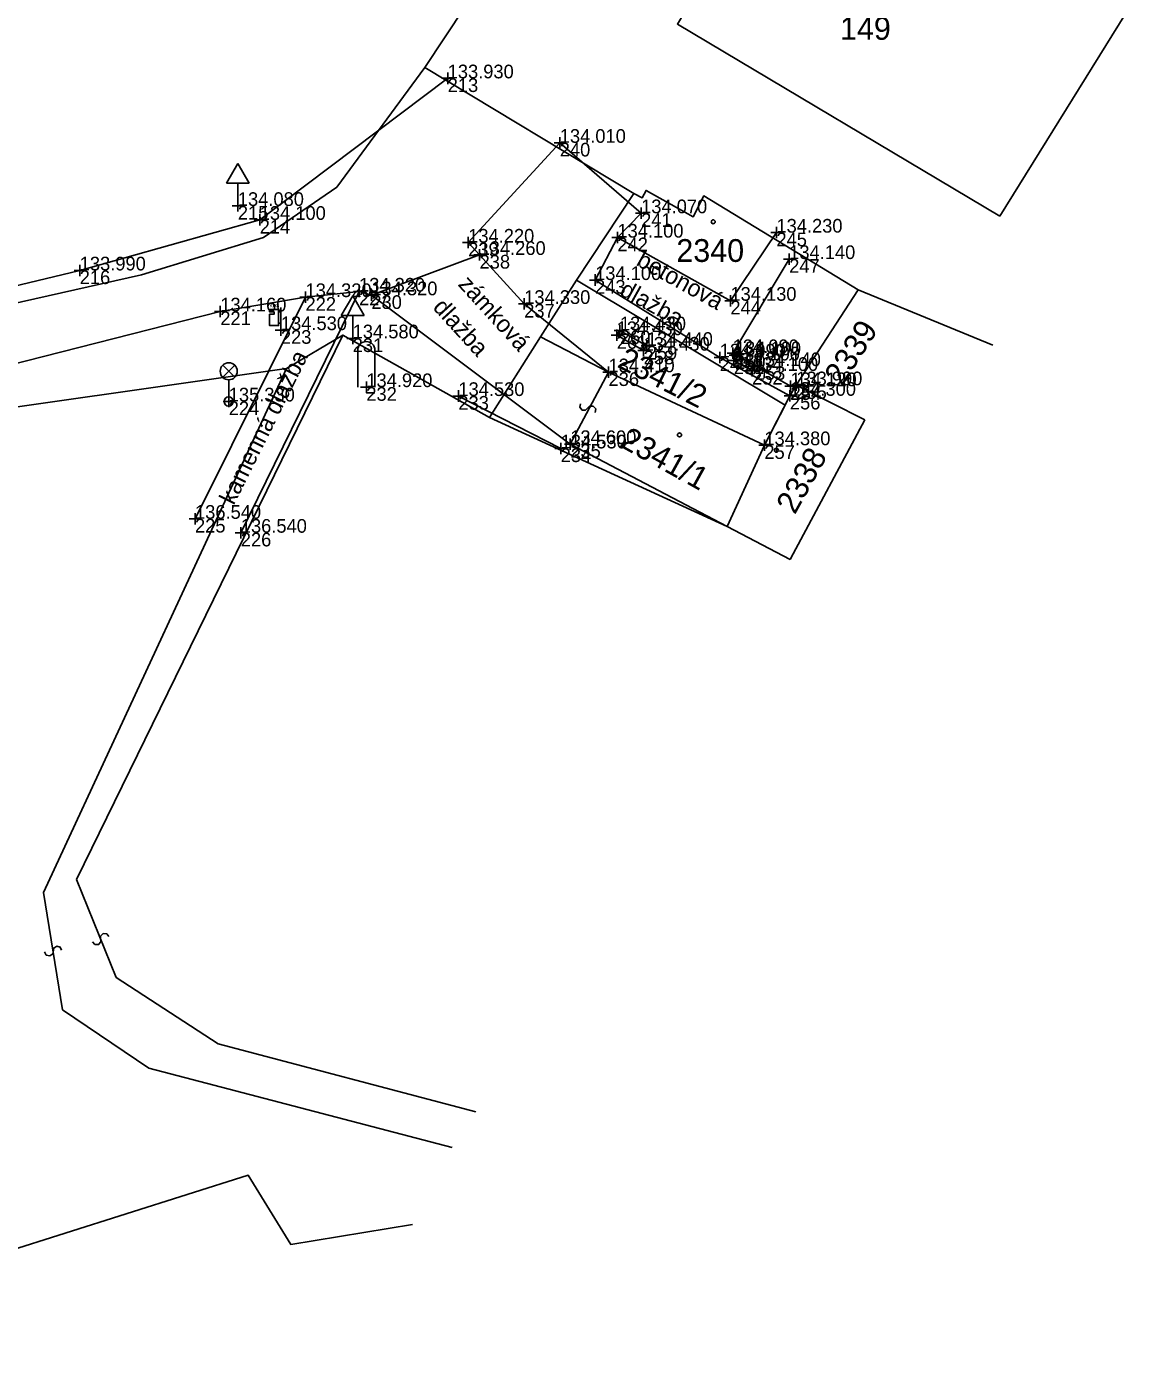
# Model space of a CAD drawing. Extents: x -747268 to -747054, y -964730 to -964532.
# Drawn here: x -747124.6 to -747076.4, y -964717 to -964658.8 of the extents above; entities that cross this region are included whole.
import ezdxf

# ---------------------------------------------------------------- set-up
doc = ezdxf.new("R2010")
doc.units = 0
for name, color, linetype in [('Body polohopisu', 7, 'Continuous'), ('Budovy', 7, 'Continuous'), ('Doplňkové značky', 7, 'Continuous'), ('KM', 7, 'Continuous'), ('Ploty_opěrné zdi', 7, 'Continuous'), ('Popisy objektů_povrchů', 7, 'Continuous'), ('Rozhraní ploch', 7, 'Continuous'), ('Stromy_porost', 7, 'Continuous'), ('Vnitřní kresba', 7, 'Continuous'), ('Výšky bodů', 7, 'Continuous'), ('Značky IS', 7, 'Continuous'), ('Čísla bodů', 7, 'Continuous')]:
    doc.layers.add(name, color=color, linetype=linetype)

msp = doc.modelspace()

# ---------------------------------------------------------------- linework, layer by layer
at = {"layer": 'Body polohopisu'}
for p, q in [((-747106.13, -964661.08), (-747106.38, -964661.08)), ((-747106.13, -964661.08), (-747106.13, -964660.83)), ((-747106.13, -964661.08), (-747105.88, -964661.08)), ((-747106.13, -964661.08), (-747106.13, -964661.33)), ((-747101.21, -964663.91), (-747101.46, -964663.91)), ((-747101.21, -964663.91), (-747101.21, -964663.66)), ((-747101.21, -964663.91), (-747100.96, -964663.91)), ((-747101.21, -964663.91), (-747101.21, -964664.16)), ((-747115.34, -964666.68), (-747115.34, -964666.43)), ((-747115.34, -964666.68), (-747115.59, -964666.68)), ((-747115.34, -964666.68), (-747115.09, -964666.68)), ((-747115.34, -964666.68), (-747115.34, -964666.93)), ((-747114.38, -964667.29), (-747114.38, -964667.04)), ((-747097.64, -964667), (-747097.89, -964667)), ((-747097.64, -964667), (-747097.64, -964666.75)), ((-747097.64, -964667), (-747097.39, -964667)), ((-747097.64, -964667), (-747097.64, -964667.25)), ((-747114.38, -964667.29), (-747114.63, -964667.29)), ((-747114.38, -964667.29), (-747114.13, -964667.29)), ((-747114.38, -964667.29), (-747114.38, -964667.54)), ((-747091.7, -964667.85), (-747091.7, -964667.6)), ((-747105.23, -964668.29), (-747105.23, -964668.04)), ((-747098.68, -964668.07), (-747098.93, -964668.07)), ((-747098.68, -964668.07), (-747098.68, -964667.82)), ((-747098.68, -964668.07), (-747098.43, -964668.07)), ((-747098.68, -964668.07), (-747098.68, -964668.32)), ((-747091.7, -964667.85), (-747091.95, -964667.85)), ((-747091.7, -964667.85), (-747091.45, -964667.85)), ((-747091.7, -964667.85), (-747091.7, -964668.1)), ((-747105.23, -964668.29), (-747105.48, -964668.29)), ((-747105.23, -964668.29), (-747104.98, -964668.29)), ((-747105.23, -964668.29), (-747105.23, -964668.54)), ((-747104.73, -964668.83), (-747104.73, -964668.58)), ((-747091.14, -964669.01), (-747091.14, -964668.76)), ((-747122.28, -964669.51), (-747122.28, -964669.26)), ((-747104.73, -964668.83), (-747104.98, -964668.83)), ((-747104.73, -964668.83), (-747104.48, -964668.83)), ((-747104.73, -964668.83), (-747104.73, -964669.08)), ((-747091.14, -964669.01), (-747091.39, -964669.01)), ((-747091.14, -964669.01), (-747090.89, -964669.01)), ((-747091.14, -964669.01), (-747091.14, -964669.26)), ((-747122.28, -964669.51), (-747122.53, -964669.51)), ((-747122.28, -964669.51), (-747122.03, -964669.51)), ((-747122.28, -964669.51), (-747122.28, -964669.76)), ((-747099.66, -964669.93), (-747099.91, -964669.93)), ((-747099.66, -964669.93), (-747099.66, -964669.68)), ((-747099.66, -964669.93), (-747099.41, -964669.93)), ((-747099.66, -964669.93), (-747099.66, -964670.18)), ((-747112.37, -964670.68), (-747112.37, -964670.43)), ((-747110.02, -964670.44), (-747110.27, -964670.44)), ((-747110.02, -964670.44), (-747110.02, -964670.19)), ((-747110.02, -964670.44), (-747109.77, -964670.44)), ((-747110.02, -964670.44), (-747110.02, -964670.69)), ((-747109.48, -964670.6), (-747109.48, -964670.35)), ((-747116.11, -964671.31), (-747116.11, -964671.06)), ((-747112.37, -964670.68), (-747112.62, -964670.68)), ((-747112.37, -964670.68), (-747112.12, -964670.68)), ((-747112.37, -964670.68), (-747112.37, -964670.93)), ((-747109.48, -964670.6), (-747109.73, -964670.6)), ((-747109.48, -964670.6), (-747109.23, -964670.6)), ((-747109.48, -964670.6), (-747109.48, -964670.85)), ((-747102.77, -964670.98), (-747103.02, -964670.98)), ((-747102.77, -964670.98), (-747102.77, -964670.73)), ((-747102.77, -964670.98), (-747102.52, -964670.98)), ((-747102.77, -964670.98), (-747102.77, -964671.23)), ((-747093.72, -964670.84), (-747093.97, -964670.84)), ((-747093.72, -964670.84), (-747093.72, -964670.59)), ((-747093.72, -964670.84), (-747093.47, -964670.84)), ((-747093.72, -964670.84), (-747093.72, -964671.09)), ((-747116.11, -964671.31), (-747116.36, -964671.31)), ((-747116.11, -964671.31), (-747115.86, -964671.31)), ((-747116.11, -964671.31), (-747116.11, -964671.56)), ((-747113.45, -964672.13), (-747113.7, -964672.13)), ((-747113.45, -964672.13), (-747113.45, -964671.88)), ((-747113.45, -964672.13), (-747113.2, -964672.13)), ((-747113.45, -964672.13), (-747113.45, -964672.38)), ((-747110.3, -964672.49), (-747110.3, -964672.24)), ((-747098.57, -964672.14), (-747098.82, -964672.14)), ((-747098.71, -964672.35), (-747098.71, -964672.1)), ((-747098.57, -964672.14), (-747098.57, -964671.89)), ((-747098.57, -964672.14), (-747098.32, -964672.14)), ((-747098.57, -964672.14), (-747098.57, -964672.39)), ((-747110.3, -964672.49), (-747110.55, -964672.49)), ((-747110.3, -964672.49), (-747110.05, -964672.49)), ((-747110.3, -964672.49), (-747110.3, -964672.74)), ((-747098.71, -964672.35), (-747098.96, -964672.35)), ((-747098.71, -964672.35), (-747098.46, -964672.35)), ((-747098.71, -964672.35), (-747098.71, -964672.6)), ((-747097.39, -964672.82), (-747097.64, -964672.82)), ((-747097.53, -964673.03), (-747097.53, -964672.78)), ((-747097.39, -964672.82), (-747097.39, -964672.57)), ((-747097.39, -964672.82), (-747097.14, -964672.82)), ((-747097.39, -964672.82), (-747097.39, -964673.07)), ((-747097.53, -964673.03), (-747097.78, -964673.03)), ((-747097.53, -964673.03), (-747097.28, -964673.03)), ((-747097.53, -964673.03), (-747097.53, -964673.28)), ((-747094.19, -964673.33), (-747094.44, -964673.33)), ((-747094.19, -964673.33), (-747094.19, -964673.08)), ((-747094.19, -964673.33), (-747093.94, -964673.33)), ((-747094.19, -964673.33), (-747094.19, -964673.58)), ((-747093.62, -964673.14), (-747093.87, -964673.14)), ((-747093.52, -964673.23), (-747093.77, -964673.23)), ((-747093.62, -964673.14), (-747093.62, -964672.89)), ((-747093.62, -964673.14), (-747093.37, -964673.14)), ((-747093.62, -964673.14), (-747093.62, -964673.39)), ((-747093.57, -964673.46), (-747093.57, -964673.21)), ((-747093.52, -964673.23), (-747093.52, -964672.98)), ((-747093.52, -964673.23), (-747093.27, -964673.23)), ((-747093.52, -964673.23), (-747093.52, -964673.48)), ((-747099.07, -964673.98), (-747099.32, -964673.98)), ((-747099.07, -964673.98), (-747099.07, -964673.73)), ((-747099.07, -964673.98), (-747098.82, -964673.98)), ((-747099.07, -964673.98), (-747099.07, -964674.23)), ((-747093.57, -964673.46), (-747093.82, -964673.46)), ((-747093.57, -964673.46), (-747093.32, -964673.46)), ((-747093.57, -964673.46), (-747093.57, -964673.71)), ((-747092.77, -964673.92), (-747093.02, -964673.92)), ((-747092.65, -964673.71), (-747092.9, -964673.71)), ((-747092.77, -964673.92), (-747092.77, -964673.67)), ((-747092.77, -964673.92), (-747092.52, -964673.92)), ((-747092.77, -964673.92), (-747092.77, -964674.17)), ((-747092.65, -964673.71), (-747092.65, -964673.46)), ((-747092.65, -964673.71), (-747092.4, -964673.71)), ((-747092.65, -964673.71), (-747092.65, -964673.96)), ((-747109.7, -964674.63), (-747109.7, -964674.38)), ((-747091.08, -964674.59), (-747091.33, -964674.59)), ((-747091.08, -964674.59), (-747091.08, -964674.34)), ((-747090.83, -964674.55), (-747091.08, -964674.55)), ((-747091.08, -964674.59), (-747090.83, -964674.59)), ((-747091.08, -964674.59), (-747091.08, -964674.84)), ((-747090.83, -964674.55), (-747090.83, -964674.3)), ((-747090.83, -964674.55), (-747090.58, -964674.55)), ((-747090.83, -964674.55), (-747090.83, -964674.8)), ((-747115.74, -964675.26), (-747115.74, -964675.01)), ((-747109.7, -964674.63), (-747109.95, -964674.63)), ((-747109.7, -964674.63), (-747109.45, -964674.63)), ((-747109.7, -964674.63), (-747109.7, -964674.88)), ((-747105.66, -964675.02), (-747105.91, -964675.02)), ((-747105.66, -964675.02), (-747105.66, -964674.77)), ((-747105.66, -964675.02), (-747105.41, -964675.02)), ((-747105.66, -964675.02), (-747105.66, -964675.27)), ((-747091.11, -964675.01), (-747091.36, -964675.01)), ((-747091.11, -964675.01), (-747091.11, -964674.76)), ((-747091.11, -964675.01), (-747090.86, -964675.01)), ((-747091.11, -964675.01), (-747091.11, -964675.26)), ((-747115.74, -964675.26), (-747115.99, -964675.26)), ((-747115.74, -964675.26), (-747115.49, -964675.26)), ((-747115.74, -964675.26), (-747115.74, -964675.51)), ((-747100.75, -964677.13), (-747100.75, -964676.88)), ((-747092.23, -964677.18), (-747092.23, -964676.93)), ((-747101.17, -964677.32), (-747101.42, -964677.32)), ((-747101.17, -964677.32), (-747101.17, -964677.07)), ((-747101.17, -964677.32), (-747100.92, -964677.32)), ((-747101.17, -964677.32), (-747101.17, -964677.57)), ((-747100.75, -964677.13), (-747101, -964677.13)), ((-747100.75, -964677.13), (-747100.5, -964677.13)), ((-747100.75, -964677.13), (-747100.75, -964677.38)), ((-747092.23, -964677.18), (-747092.48, -964677.18)), ((-747092.23, -964677.18), (-747091.98, -964677.18)), ((-747092.23, -964677.18), (-747092.23, -964677.43)), ((-747117.22, -964680.41), (-747117.47, -964680.41)), ((-747117.22, -964680.41), (-747117.22, -964680.16)), ((-747117.22, -964680.41), (-747116.97, -964680.41)), ((-747117.22, -964680.41), (-747117.22, -964680.66)), ((-747115.21, -964681.02), (-747115.21, -964680.77)), ((-747115.21, -964681.02), (-747115.46, -964681.02)), ((-747115.21, -964681.02), (-747114.96, -964681.02)), ((-747115.21, -964681.02), (-747115.21, -964681.27))]:
    msp.add_line(p, q, dxfattribs=at)
at = {"layer": 'Budovy'}
for points in [[(-747091.14, -964669.01), (-747093.62, -964673.14), (-747091.08, -964674.59)], [(-747100.75, -964677.13), (-747099.07, -964673.98), (-747092.23, -964677.18), (-747091.11, -964675.01), (-747090.83, -964674.55)]]:
    msp.add_lwpolyline(points, dxfattribs=at)
at = {"layer": 'Doplňkové značky'}
for p, q in [((-747115.34, -964664.814), (-747115.84, -964665.68)), ((-747115.34, -964664.814), (-747114.84, -964665.68)), ((-747115.84, -964665.68), (-747114.84, -964665.68)), ((-747115.34, -964666.68), (-747115.34, -964665.68)), ((-747115.59, -964666.68), (-747115.09, -964666.68)), ((-747110.3, -964670.624), (-747110.8, -964671.49)), ((-747110.3, -964670.624), (-747109.8, -964671.49)), ((-747113.55, -964671.33), (-747113.45, -964671.33)), ((-747113.45, -964672.13), (-747113.45, -964671.13)), ((-747110.8, -964671.49), (-747109.8, -964671.49)), ((-747110.3, -964672.49), (-747110.3, -964671.49)), ((-747113.55, -964671.83), (-747113.45, -964671.83)), ((-747110.55, -964672.49), (-747110.05, -964672.49)), ((-747116.004, -964674.198), (-747115.476, -964673.67)), ((-747115.468, -964674.195), (-747115.996, -964673.666)), ((-747115.74, -964674.31), (-747115.74, -964675.06))]:
    msp.add_line(p, q, dxfattribs=at)
msp.add_lwpolyline([(-747113.55, -964671.23), (-747113.95, -964671.23), (-747113.95, -964671.33), (-747113.75, -964671.33), (-747113.75, -964671.43), (-747113.95, -964671.43), (-747113.95, -964671.93), (-747113.55, -964671.93)], close=True, dxfattribs=at)
for centre, radius in [((-747115.74, -964673.935), 0.375), ((-747115.74, -964675.26), 0.2)]:
    msp.add_circle(centre, radius, dxfattribs=at)
at = {"layer": 'KM'}
for p, q in [((-747097.96, -964666.13), (-747107.13, -964660.6)), ((-747097.96, -964666.13), (-747100.47, -964669.94)), ((-747100.47, -964669.94), (-747102.05, -964672.43)), ((-747100.47, -964669.94), (-747091.317, -964675.428)), ((-747088.11, -964670.36), (-747090.83, -964674.55)), ((-747102.05, -964672.43), (-747104.3, -964675.97)), ((-747087.82, -964676.07), (-747090.83, -964674.55)), ((-747091.317, -964675.428), (-747092.23, -964677.18)), ((-747104.3, -964675.97), (-747093.87, -964680.75)), ((-747092.23, -964677.18), (-747093.87, -964680.75)), ((-747093.87, -964680.75), (-747091.1, -964682.2))]:
    msp.add_line(p, q, dxfattribs=at)
for points in [[(-747170.03, -964639.52), (-747191.65, -964675.11), (-747205.07, -964701.27), (-747194.33, -964694.71), (-747168.43, -964681.69), (-747141.95, -964674.74), (-747119.57, -964669.71), (-747114.21, -964668.06), (-747110.99, -964665.85), (-747107.13, -964660.6)], [(-747107.13, -964660.6), (-747104.48, -964656.59), (-747121.632, -964647.15), (-747121.66, -964647.17)], [(-747089.3, -964650.74), (-747090.77, -964649.84), (-747096.05, -964658.7), (-747081.9, -964667.13)], [(-747081.9, -964667.13), (-747076.38, -964658.25), (-747076.7, -964658.06)], [(-747088.11, -964670.36), (-747094.89, -964666.24), (-747095.36, -964667.16), (-747097.42, -964666), (-747097.6, -964666.33), (-747097.96, -964666.13)], [(-747082.2, -964672.79), (-747088.11, -964670.36)], [(-747104.3, -964675.97), (-747110.73, -964672.35), (-747113.2, -964673.81), (-747141.15, -964677.79), (-747165.83, -964684.28), (-747192.76, -964697.48), (-747203.13, -964704.43), (-747209.73, -964711.996)], [(-747092.23, -964677.18), (-747099.07, -964673.98), (-747102.05, -964672.43)], [(-747090.83, -964674.55), (-747091.11, -964675.01), (-747091.317, -964675.428)], [(-747087.82, -964676.07), (-747090.96, -964681.94), (-747091.1, -964682.2)], [(-747201.228, -964716.992), (-747197.7, -964710.92), (-747185.17, -964707.62), (-747166.03, -964703.32), (-747141.08, -964710.85), (-747134.49, -964709.31), (-747125.59, -964712.6), (-747114.89, -964709.21), (-747113.01, -964712.26), (-747107.669, -964711.374)]]:
    msp.add_lwpolyline(points, dxfattribs=at)
for centre in [(-747094.475, -964667.375), (-747095.955, -964676.727), (-747091.703, -964677.4)]:
    msp.add_circle(centre, 0.0875, dxfattribs=at)
at = {"layer": 'Ploty_opěrné zdi'}
for points in [[(-747098.68, -964668.07), (-747099.66, -964669.93), (-747094.19, -964673.33), (-747091.11, -964675.01)], [(-747105.66, -964675.02), (-747101.17, -964677.32)]]:
    msp.add_lwpolyline(points, dxfattribs=at)
at = {"layer": 'Rozhraní ploch'}
for points in [[(-747106.13, -964661.08), (-747114.38, -964667.29)], [(-747099.07, -964673.98), (-747102.77, -964670.98), (-747104.73, -964668.83), (-747105.23, -964668.29), (-747101.21, -964663.91), (-747097.64, -964667), (-747098.68, -964668.07), (-747093.72, -964670.84), (-747091.7, -964667.85)], [(-747114.38, -964667.29), (-747122.28, -964669.51), (-747137.71, -964673.21), (-747150.36, -964676.79)], [(-747109.48, -964670.6), (-747104.73, -964668.83)], [(-747115.21, -964681.02), (-747110.02, -964670.44), (-747109.48, -964670.6), (-747100.75, -964677.13)], [(-747112.37, -964670.68), (-747110.02, -964670.44)], [(-747149.88, -964679.95), (-747128.54, -964674.47), (-747116.11, -964671.31), (-747112.37, -964670.68), (-747117.22, -964680.41)]]:
    msp.add_lwpolyline(points, dxfattribs=at)
at = {"layer": 'Stromy_porost'}
for p, q in [((-747110.075, -964674.63), (-747110.075, -964673.005)), ((-747109.325, -964674.63), (-747109.325, -964673.005))]:
    msp.add_line(p, q, dxfattribs=at)
msp.add_lwpolyline([(-747109.7, -964674.63), (-747109.7, -964674.88), (-747109.325, -964674.88)], dxfattribs=at)
msp.add_arc((-747109.7, -964673.005), 0.375, 0, 179.99999, dxfattribs=at)
at = {"layer": 'Vnitřní kresba'}
for p, q in [((-747122.42, -964696.24), (-747110.73, -964672.35)), ((-747113.2, -964673.81), (-747123.87, -964696.8)), ((-747100.75, -964677.13), (-747099.07, -964673.98)), ((-747100.75, -964677.13), (-747093.87, -964680.75)), ((-747120.68, -964700.54), (-747122.42, -964696.24)), ((-747123.87, -964696.8), (-747123.03, -964701.95)), ((-747116.21, -964703.45), (-747120.68, -964700.54)), ((-747123.03, -964701.95), (-747119.24, -964704.52)), ((-747104.892, -964706.43), (-747116.21, -964703.45)), ((-747119.24, -964704.52), (-747105.928, -964708.004))]:
    msp.add_line(p, q, dxfattribs=at)
for points in [[(-747099.655, -964675.741), (-747099.634, -964675.584), (-747099.747, -964675.462), (-747099.899, -964675.466), (-747100.081, -964675.644), (-747100.233, -964675.637), (-747100.333, -964675.511), (-747100.307, -964675.367)], [(-747121.719, -964698.972), (-747121.616, -964699.093), (-747121.45, -964699.09), (-747121.351, -964698.975), (-747121.363, -964698.72), (-747121.255, -964698.612), (-747121.095, -964698.623), (-747121.005, -964698.738)], [(-747123.824, -964699.41), (-747123.751, -964699.55), (-747123.588, -964699.584), (-747123.466, -964699.493), (-747123.421, -964699.243), (-747123.292, -964699.161), (-747123.138, -964699.207), (-747123.076, -964699.338)]]:
    msp.add_lwpolyline(points, dxfattribs=at)
at = {"layer": 'Značky IS'}
for points in [[(-747098.57, -964672.14), (-747098.71, -964672.35), (-747097.53, -964673.03), (-747097.39, -964672.82), (-747098.57, -964672.14)], [(-747093.52, -964673.23), (-747093.57, -964673.46), (-747092.77, -964673.92), (-747092.65, -964673.71)]]:
    msp.add_lwpolyline(points, dxfattribs=at)

# ---------------------------------------------------------------- texts
at = {"layer": 'Doplňkové značky'}
msp.add_text('koš', height=0.2, dxfattribs=at).set_placement((-747113.95, -964671.13))
at = {"layer": 'KM'}
for s, p in [('149', (-747088.91, -964659.39)), ('2340', (-747096.094, -964669.136))]:
    msp.add_text(s, height=1, dxfattribs=at).set_placement(p)
for s, rotation, p in [('2339', 57.31945, (-747088.818, -964674.621)), ('2341/2', 333, (-747098.733, -964673.728)), ('2341/1', 331, (-747098.631, -964677.209)), ('2338', 61, (-747090.89, -964680.256))]:
    msp.add_text(s, height=1, rotation=rotation, dxfattribs=at).set_placement(p)
at = {"layer": 'Popisy objektů_povrchů'}
for s, rotation, p in [('betonová', 330.81805, (-747097.899, -964669.255)), ('zámková', 312.35317, (-747105.709, -964670.147)), ('dlažba', 330.81805, (-747098.63, -964670.565)), ('dlažba', 312.35317, (-747106.818, -964671.158)), ('kamenná dlažba', 63.50566, (-747115.519, -964679.843))]:
    msp.add_text(s, height=0.75, rotation=rotation, dxfattribs=at).set_placement(p)
at = {"layer": 'Výšky bodů'}
for s, p in [('133.930', (-747106.13, -964661.08)), ('134.010', (-747101.21, -964663.91)), ('134.080', (-747115.34, -964666.68)), ('134.070', (-747097.64, -964667)), ('134.100', (-747114.38, -964667.29)), ('134.100', (-747098.68, -964668.07)), ('134.230', (-747091.7, -964667.85)), ('134.220', (-747105.23, -964668.29)), ('134.260', (-747104.73, -964668.83)), ('134.140', (-747091.14, -964669.01)), ('133.990', (-747122.28, -964669.51)), ('134.100', (-747099.66, -964669.93)), ('134.320', (-747110.02, -964670.44)), ('134.320', (-747112.37, -964670.68)), ('134.320', (-747109.48, -964670.6)), ('134.330', (-747102.77, -964670.98)), ('134.130', (-747093.72, -964670.84)), ('134.160', (-747116.11, -964671.31)), ('134.530', (-747113.45, -964672.13)), ('134.430', (-747098.57, -964672.14)), ('134.580', (-747110.3, -964672.49)), ('134.430', (-747098.71, -964672.35)), ('134.440', (-747097.39, -964672.82)), ('134.430', (-747097.53, -964673.03)), ('134.090', (-747094.19, -964673.33)), ('134.090', (-747093.62, -964673.14)), ('134.100', (-747093.57, -964673.46)), ('134.100', (-747093.52, -964673.23)), ('134.410', (-747099.07, -964673.98)), ('134.100', (-747092.77, -964673.92)), ('134.140', (-747092.65, -964673.71)), ('134.920', (-747109.7, -964674.63)), ('134.120', (-747091.08, -964674.59)), ('133.990', (-747090.83, -964674.55)), ('134.530', (-747105.66, -964675.02)), ('134.300', (-747091.11, -964675.01)), ('135.330', (-747115.74, -964675.26)), ('134.530', (-747101.17, -964677.32)), ('134.600', (-747100.75, -964677.13)), ('134.380', (-747092.23, -964677.18)), ('136.540', (-747117.22, -964680.41)), ('136.540', (-747115.21, -964681.02))]:
    msp.add_text(s, height=0.6, dxfattribs=at).set_placement(p)
at = {"layer": 'Čísla bodů'}
for s, p in [('213', (-747106.13, -964661.68)), ('240', (-747101.21, -964664.51)), ('215', (-747115.34, -964667.28)), ('241', (-747097.64, -964667.6)), ('214', (-747114.38, -964667.89)), ('242', (-747098.68, -964668.67)), ('245', (-747091.7, -964668.45)), ('239', (-747105.23, -964668.89)), ('238', (-747104.73, -964669.43)), ('247', (-747091.14, -964669.61)), ('216', (-747122.28, -964670.11)), ('243', (-747099.66, -964670.53)), ('227', (-747110.02, -964671.04)), ('222', (-747112.37, -964671.28)), ('230', (-747109.48, -964671.2)), ('237', (-747102.77, -964671.58)), ('244', (-747093.72, -964671.44)), ('221', (-747116.11, -964671.91)), ('223', (-747113.45, -964672.73)), ('260', (-747098.57, -964672.74)), ('231', (-747110.3, -964673.09)), ('261', (-747098.71, -964672.95)), ('259', (-747097.39, -964673.42)), ('258', (-747097.53, -964673.63)), ('249', (-747094.19, -964673.93)), ('248', (-747093.62, -964673.74)), ('250', (-747093.52, -964673.83)), ('236', (-747099.07, -964674.58)), ('251', (-747093.57, -964674.06)), ('252', (-747092.77, -964674.52)), ('253', (-747092.65, -964674.31)), ('254', (-747091.08, -964675.19)), ('255', (-747090.83, -964675.15)), ('232', (-747109.7, -964675.23)), ('233', (-747105.66, -964675.62)), ('256', (-747091.11, -964675.61)), ('224', (-747115.74, -964675.86)), ('234', (-747101.17, -964677.92)), ('235', (-747100.75, -964677.73)), ('257', (-747092.23, -964677.78)), ('225', (-747117.22, -964681.01)), ('226', (-747115.21, -964681.62))]:
    msp.add_text(s, height=0.6, dxfattribs=at).set_placement(p)

doc.saveas('drawing.dxf')
